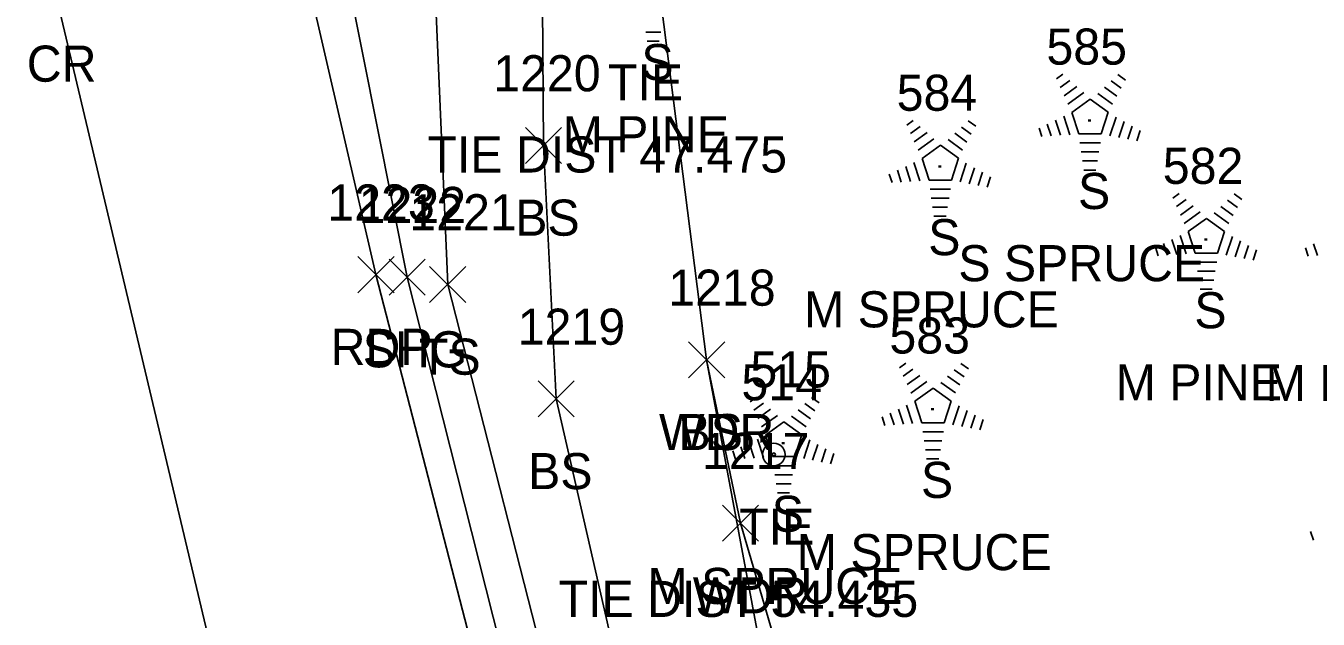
# Model space of a CAD drawing. Extents: x 1545627 to 1546562, y 571176 to 576667.
# Drawn here: x 1546146.3 to 1546217.9, y 571977 to 572009.9 of the extents above; entities that cross this region are included whole.
import ezdxf

# ---------------------------------------------------------------- set-up
doc = ezdxf.new("R2010")
doc.units = 0
for name, color, linetype in [('C_A', 7, 'Continuous'), ('C_C', 7, 'Continuous'), ('C_I', 7, 'Continuous'), ('CBP', 7, 'Continuous'), ('L_A', 7, 'Continuous'), ('L_C', 7, 'Continuous'), ('L_I', 7, 'Continuous'), ('L_TIC', 7, 'Continuous'), ('LAWA', 7, 'Continuous'), ('LELB', 7, 'Continuous'), ('LTC', 7, 'Continuous'), ('P_A', 7, 'Continuous'), ('P_I', 7, 'Continuous'), ('P_TIC', 7, 'Continuous'), ('PET', 7, 'Continuous'), ('PRC', 7, 'Continuous'), ('PSU', 7, 'Continuous')]:
    doc.layers.add(name, color=color, linetype=linetype)

msp = doc.modelspace()

# ---------------------------------------------------------------- linework, layer by layer
at = {"layer": 'CBP'}
for radius in [0.625, 0.0833]:
    msp.add_circle((1546187.703, 571986.142), radius, dxfattribs=at)
at = {"layer": 'L_TIC'}
for points in [[(1546173.94, 572002.263), (1546175.94, 572004.263)], [(1546175.94, 572002.263), (1546173.94, 572004.263)], [(1546168.64, 571994.561), (1546170.64, 571996.561)], [(1546170.64, 571994.561), (1546168.64, 571996.561)], [(1546182.98, 571990.384), (1546184.98, 571992.384)], [(1546184.98, 571990.384), (1546182.98, 571992.384)], [(1546182.98, 571990.384), (1546184.98, 571992.384)], [(1546184.98, 571990.384), (1546182.98, 571992.384)], [(1546174.652, 571988.222), (1546176.652, 571990.222)], [(1546176.652, 571988.222), (1546174.652, 571990.222)], [(1546184.852, 571981.338), (1546186.852, 571983.338)], [(1546186.852, 571981.338), (1546184.852, 571983.338)]]:
    msp.add_lwpolyline(points, dxfattribs=at)
at = {"layer": 'LAWA'}
msp.add_lwpolyline([(1546228.586, 571855.541), (1546209.815, 571899.546), (1546194.552, 571952.56), (1546185.852, 571982.338), (1546183.98, 571991.384), (1546179.112, 572029.569), (1546170.944, 572048.245), (1546164.758, 572064.391), (1546155.771, 572091.279), (1546144.336, 572123.946)], dxfattribs=at)
at = {"layer": 'LELB'}
for points in [[(1546347.404, 571535.241), (1546326.62, 571574.77), (1546309.351, 571609.13), (1546297.635, 571636.432), (1546292.788, 571646.222), (1546275.729, 571689.363), (1546263.627, 571715.111), (1546250.323, 571751.347), (1546233.4, 571797.155), (1546220.817, 571841.735), (1546218.613, 571853), (1546198.39, 571897.178), (1546185.101, 571947.883), (1546175.652, 571989.222), (1546174.94, 572003.263), (1546174.777, 572026.811), (1546167.554, 572047.439), (1546164.758, 572064.391), (1546160.424, 572092.892), (1546150.118, 572129.232)], [(1546346.375, 571534.64), (1546325.48, 571574.254), (1546308.892, 571608.63), (1546296.212, 571635.99), (1546273.967, 571687.639), (1546262.69, 571714.717), (1546248.75, 571750.385), (1546231.961, 571796.63), (1546217.305, 571838.705), (1546210.358, 571854.991), (1546196.649, 571896.999), (1546182.096, 571946.809), (1546169.64, 571995.561), (1546168.24, 572028.129), (1546158.043, 572044.974), (1546148.167, 572086.529), (1546140.639, 572120.601)], [(1546290.318, 571657.048), (1546276.567, 571693.199), (1546283.409, 571696.029), (1546285.218, 571707.812), (1546280.59, 571717.609), (1546272.325, 571717.419), (1546265.003, 571715.531), (1546255.381, 571753.558), (1546251.916, 571771.022), (1546251.669, 571784.619), (1546239.773, 571800.023), (1546225.642, 571844.556), (1546223.567, 571853.749), (1546206.909, 571899.078), (1546191.554, 571950.783), (1546183.98, 571991.384)]]:
    msp.add_lwpolyline(points, dxfattribs=at)
at = {"layer": 'LTC'}
for p, q in [((1546181.439, 572009.545), (1546180.607, 572009.545)), ((1546181.355, 572009.045), (1546180.68, 572009.045)), ((1546203.359, 572006.948), (1546203.714, 572007.205)), ((1546203.569, 572006.482), (1546204.098, 572006.867)), ((1546203.778, 572006.017), (1546204.482, 572006.528)), ((1546206.386, 572006.84), (1546206.936, 572006.441)), ((1546206.758, 572007.188), (1546207.177, 572006.884)), ((1546203.988, 572005.551), (1546204.866, 572006.189)), ((1546204.213, 572005.096), (1546205.224, 572005.83)), ((1546205.224, 572005.83), (1546206.221, 572005.105)), ((1546205.644, 572006.143), (1546206.454, 572005.555)), ((1546206.015, 572006.492), (1546206.695, 572005.998)), ((1546204.213, 572005.096), (1546204.6, 572003.902)), ((1546206.221, 572005.105), (1546205.83, 572003.902)), ((1546195.065, 572004.391), (1546195.419, 572004.649)), ((1546198.463, 572004.632), (1546198.882, 572004.327)), ((1546202.847, 572004.444), (1546203.059, 572003.792)), ((1546203.303, 572004.66), (1546203.574, 572003.825)), ((1546203.758, 572004.877), (1546204.089, 572003.857)), ((1546206.659, 572004.835), (1546206.321, 572003.795)), ((1546207.103, 572004.584), (1546206.816, 572003.7)), ((1546195.274, 572003.926), (1546195.804, 572004.31)), ((1546195.484, 572003.46), (1546196.188, 572003.971)), ((1546197.721, 572003.935), (1546198.4, 572003.441)), ((1546198.092, 572004.283), (1546198.641, 572003.884)), ((1546202.392, 572004.227), (1546202.544, 572003.759)), ((1546205.83, 572003.902), (1546204.6, 572003.902)), ((1546207.548, 572004.334), (1546207.311, 572003.605)), ((1546207.992, 572004.084), (1546207.805, 572003.51)), ((1546195.694, 572002.994), (1546196.572, 572003.632)), ((1546195.918, 572002.539), (1546196.93, 572003.274)), ((1546196.93, 572003.274), (1546197.927, 572002.549)), ((1546197.35, 572003.587), (1546198.159, 572002.998)), ((1546205.792, 572003.402), (1546204.647, 572003.402)), ((1546195.464, 572002.32), (1546195.794, 572001.301)), ((1546195.918, 572002.539), (1546196.305, 572001.346)), ((1546197.927, 572002.549), (1546197.536, 572001.346)), ((1546198.364, 572002.278), (1546198.026, 572001.238)), ((1546205.708, 572002.902), (1546204.72, 572002.902)), ((1546205.624, 572002.402), (1546204.793, 572002.402)), ((1546194.097, 572001.67), (1546194.249, 572001.203)), ((1546194.553, 572001.887), (1546194.764, 572001.235)), ((1546195.008, 572002.104), (1546195.279, 572001.268)), ((1546198.809, 572002.028), (1546198.521, 572001.143)), ((1546199.254, 572001.778), (1546199.016, 572001.048)), ((1546199.698, 572001.527), (1546199.511, 572000.953)), ((1546205.54, 572001.902), (1546204.865, 572001.902)), ((1546197.536, 572001.346), (1546196.305, 572001.346)), ((1546197.497, 572000.846), (1546196.353, 572000.846)), ((1546197.414, 572000.346), (1546196.425, 572000.346)), ((1546209.803, 572000.341), (1546210.158, 572000.598)), ((1546210.013, 571999.875), (1546210.542, 572000.259)), ((1546212.83, 572000.233), (1546213.38, 571999.834)), ((1546213.202, 572000.581), (1546213.621, 572000.277)), ((1546197.33, 571999.846), (1546196.498, 571999.846)), ((1546210.222, 571999.409), (1546210.926, 571999.921)), ((1546210.432, 571998.944), (1546211.31, 571999.582)), ((1546212.088, 571999.536), (1546212.898, 571998.947)), ((1546212.46, 571999.884), (1546213.139, 571999.391)), ((1546197.246, 571999.346), (1546196.571, 571999.346)), ((1546210.657, 571998.489), (1546211.668, 571999.223)), ((1546211.668, 571999.223), (1546212.665, 571998.498)), ((1546209.747, 571998.053), (1546210.018, 571997.218)), ((1546210.202, 571998.269), (1546210.533, 571997.25)), ((1546210.657, 571998.489), (1546211.044, 571997.295)), ((1546212.665, 571998.498), (1546212.274, 571997.295)), ((1546213.103, 571998.227), (1546212.765, 571997.188)), ((1546213.547, 571997.977), (1546213.26, 571997.092)), ((1546208.836, 571997.62), (1546208.988, 571997.152)), ((1546209.291, 571997.837), (1546209.503, 571997.185)), ((1546212.274, 571997.295), (1546211.044, 571997.295)), ((1546213.992, 571997.727), (1546213.755, 571996.997)), ((1546214.436, 571997.477), (1546214.25, 571996.902)), ((1546217.146, 571997.594), (1546217.298, 571997.126)), ((1546217.601, 571997.81), (1546217.813, 571997.159)), ((1546212.236, 571996.795), (1546211.091, 571996.795)), ((1546212.152, 571996.295), (1546211.164, 571996.295)), ((1546212.068, 571995.795), (1546211.237, 571995.795)), ((1546211.985, 571995.295), (1546211.31, 571995.295)), ((1546194.661, 571990.942), (1546195.016, 571991.199)), ((1546194.871, 571990.477), (1546195.4, 571990.861)), ((1546197.688, 571990.834), (1546198.238, 571990.435)), ((1546198.059, 571991.182), (1546198.478, 571990.878)), ((1546195.08, 571990.011), (1546195.784, 571990.522)), ((1546195.29, 571989.545), (1546196.168, 571990.183)), ((1546196.946, 571990.137), (1546197.756, 571989.549)), ((1546197.317, 571990.486), (1546197.996, 571989.992)), ((1546195.514, 571989.09), (1546196.526, 571989.824)), ((1546196.526, 571989.824), (1546197.523, 571989.099)), ((1546186.394, 571989.066), (1546186.749, 571989.324)), ((1546186.604, 571988.601), (1546187.133, 571988.985)), ((1546186.813, 571988.135), (1546187.517, 571988.646)), ((1546189.421, 571988.958), (1546189.971, 571988.559)), ((1546189.792, 571989.307), (1546190.212, 571989.002)), ((1546194.604, 571988.654), (1546194.876, 571987.819)), ((1546195.06, 571988.871), (1546195.391, 571987.852)), ((1546195.514, 571989.09), (1546195.901, 571987.897)), ((1546197.523, 571989.099), (1546197.132, 571987.897)), ((1546197.961, 571988.829), (1546197.623, 571987.789)), ((1546187.023, 571987.669), (1546187.901, 571988.307)), ((1546187.247, 571987.214), (1546188.259, 571987.949)), ((1546188.259, 571987.949), (1546189.256, 571987.224)), ((1546188.679, 571988.262), (1546189.489, 571987.673)), ((1546189.05, 571988.61), (1546189.729, 571988.116)), ((1546193.694, 571988.221), (1546193.846, 571987.753)), ((1546194.149, 571988.438), (1546194.361, 571987.786)), ((1546198.405, 571988.578), (1546198.118, 571987.694)), ((1546198.85, 571988.328), (1546198.613, 571987.599)), ((1546199.294, 571988.078), (1546199.107, 571987.504)), ((1546187.247, 571987.214), (1546187.634, 571986.021)), ((1546189.256, 571987.224), (1546188.865, 571986.021)), ((1546197.132, 571987.897), (1546195.901, 571987.897)), ((1546197.094, 571987.397), (1546195.949, 571987.397)), ((1546185.882, 571986.562), (1546186.094, 571985.911)), ((1546186.337, 571986.779), (1546186.609, 571985.943)), ((1546186.793, 571986.995), (1546187.124, 571985.976)), ((1546189.694, 571986.953), (1546189.356, 571985.913)), ((1546190.138, 571986.703), (1546189.851, 571985.818)), ((1546197.01, 571986.897), (1546196.021, 571986.897)), ((1546185.427, 571986.346), (1546185.579, 571985.878)), ((1546188.865, 571986.021), (1546187.634, 571986.021)), ((1546190.583, 571986.453), (1546190.346, 571985.723)), ((1546191.027, 571986.202), (1546190.84, 571985.628)), ((1546196.926, 571986.397), (1546196.094, 571986.397)), ((1546196.842, 571985.897), (1546196.167, 571985.897)), ((1546188.827, 571985.521), (1546187.682, 571985.521)), ((1546188.743, 571985.021), (1546187.754, 571985.021)), ((1546188.659, 571984.521), (1546187.827, 571984.521)), ((1546188.575, 571984.021), (1546187.9, 571984.021)), ((1546217.434, 571981.866), (1546217.586, 571981.398))]:
    msp.add_line(p, q, dxfattribs=at)
at = {"layer": 'P_TIC'}
for points in [[(1546164.665, 571995.104), (1546166.665, 571997.104)], [(1546166.665, 571995.104), (1546164.665, 571997.104)], [(1546166.396, 571994.967), (1546168.396, 571996.967)], [(1546168.396, 571994.967), (1546166.396, 571996.967)]]:
    msp.add_lwpolyline(points, dxfattribs=at)
at = {"layer": 'PET'}
msp.add_lwpolyline([(1546178.724, 571945.469), (1546165.665, 571996.104), (1546159.154, 572024.255), (1546153.989, 572044.121), (1546144.875, 572085.592), (1546137.672, 572117.642)], dxfattribs=at)
at = {"layer": 'PRC'}
msp.add_lwpolyline([(1546157.434, 571971.538), (1546147.892, 572011.795), (1546142.502, 572037.302), (1546134.127, 572076.488), (1546128.258, 572103.577)], dxfattribs=at)
at = {"layer": 'PSU'}
msp.add_lwpolyline([(1546344.909, 571533.751), (1546324.237, 571573.752), (1546307.569, 571607.607), (1546295.255, 571635.337), (1546272.392, 571686.555), (1546261.3, 571714.23), (1546246.813, 571749.297), (1546229.824, 571796.031), (1546214.931, 571836.379), (1546208.219, 571856.105), (1546194.623, 571896.648), (1546180.076, 571945.808), (1546167.396, 571995.967), (1546161.656, 572024.838), (1546155.575, 572044.541)], dxfattribs=at)

# ---------------------------------------------------------------- texts
at = {"layer": 'C_A'}
for p in [(1546178.517, 572005.764), (1546185.782, 571981.142)]:
    msp.add_text('TIE', height=2, dxfattribs=at).set_placement(p)
at = {"layer": 'C_C'}
for s, p in [('TIE DIST 47.475', (1546168.517, 572001.764)), ('TIE DIST 54.435', (1546175.782, 571977.142))]:
    msp.add_text(s, height=2, dxfattribs=at).set_placement(p)
at = {"layer": 'C_I'}
msp.add_text('514', height=2, dxfattribs=at).set_placement((1546185.908, 571989.142))
at = {"layer": 'L_A'}
for s, p in [('S', (1546180.364, 572006.882)), ('S', (1546204.55, 571999.74)), ('BS', (1546173.381, 571998.263)), ('S', (1546196.255, 571997.183)), ('S', (1546210.994, 571993.133)), ('TS', (1546168.05, 571990.561)), ('WDR', (1546181.342, 571986.384)), ('BS', (1546182.421, 571986.384)), ('BS', (1546174.093, 571984.222)), ('S', (1546195.852, 571983.734)), ('S', (1546187.585, 571981.858)), ('WDR', (1546183.214, 571977.338))]:
    msp.add_text(s, height=2, dxfattribs=at).set_placement(p)
at = {"layer": 'L_C'}
for s, p in [('M PINE', (1546176.002, 572002.882)), ('S SPRUCE', (1546197.92, 571995.74)), ('M SPRUCE', (1546189.374, 571993.183)), ('M PINE', (1546206.632, 571989.133)), ('M PINE', (1546214.942, 571989.106)), ('M SPRUCE', (1546188.97, 571979.734)), ('M SPRUCE', (1546180.703, 571977.858))]:
    msp.add_text(s, height=2, dxfattribs=at).set_placement(p)
at = {"layer": 'L_I'}
for s, p in [('585', (1546202.802, 572007.74)), ('1220', (1546172.161, 572006.263)), ('584', (1546194.507, 572005.183)), ('582', (1546209.246, 572001.133)), ('1221', (1546167.514, 571998.561)), ('1218', (1546181.854, 571994.384)), ('1218', (1546181.854, 571994.384)), ('1219', (1546173.518, 571992.222)), ('583', (1546194.104, 571991.734)), ('515', (1546186.404, 571989.858)), ('1217', (1546183.726, 571985.338))]:
    msp.add_text(s, height=2, dxfattribs=at).set_placement(p)
at = {"layer": 'LTC'}
for p in [(1546205.107, 572004.844), (1546196.812, 572002.287), (1546211.551, 571998.237), (1546196.409, 571988.838), (1546188.142, 571986.962)]:
    msp.add_text('.', height=1.037, rotation=270, dxfattribs=at).set_placement(p)
at = {"layer": 'P_A'}
for s, p in [('CR', (1546146.325, 572006.795)), ('RDP', (1546163.153, 571991.104)), ('SHG', (1546164.932, 571990.967))]:
    msp.add_text(s, height=2, dxfattribs=at).set_placement(p)
at = {"layer": 'P_I'}
for s, p in [('1223', (1546162.972, 571999.104)), ('1222', (1546164.703, 571998.967))]:
    msp.add_text(s, height=2, dxfattribs=at).set_placement(p)

doc.saveas('drawing.dxf')
